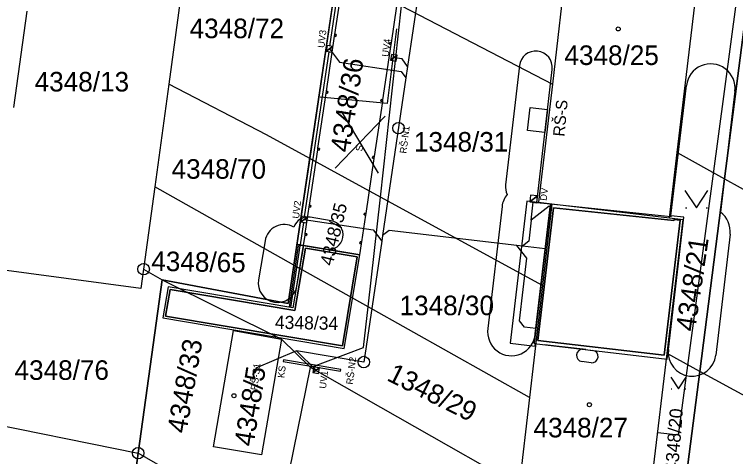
# Model space of a CAD drawing. Extents: x -735036 to -734743, y -1144813 to -1144181.
# Drawn here: x -734898.4 to -734835.7, y -1144564.1 to -1144525.7 of the extents above; entities that cross this region are included whole.
import ezdxf

# ---------------------------------------------------------------- set-up
doc = ezdxf.new("R2010")
doc.units = 0
for name, color, linetype in [('A3_BOURANÉ OBJEKTY', 7, 'Continuous'), ('A3_Netisk', 7, 'Continuous'), ('A3_ODVODŇOVACÍ ŽLAB', 7, 'Continuous'), ('A3_SIT_OBJEKTY_N01', 7, 'Continuous'), ('A3_SIT_PNB', 7, 'Continuous'), ('CKKOTY', 7, 'Continuous'), ('CKPLYN_POTRUBI_NT_PODZ_N', 7, 'Continuous'), ('CKSTENY_SRAF', 7, 'Continuous'), ('CKTEXTY_MALE', 7, 'Continuous'), ('Katastr_HRANICE DRÁHY', 7, 'Continuous'), ('Katastr_Hranice parcel', 7, 'Continuous'), ('Katastr_Parcelní čísla', 7, 'Continuous'), ('Katastr_Značky kultur', 7, 'Continuous'), ('SO01_CKKANALIZACE_JEDNOTNA_PODZ_N', 7, 'Continuous'), ('SO05_CKKANALIZACE_JEDNOTNA_PODZ_N', 7, 'Continuous')]:
    doc.layers.add(name, color=color, linetype=linetype)

msp = doc.modelspace()

# ---------------------------------------------------------------- linework, layer by layer
for p, q in [((-734871.293, -1144528.872), (-734870.725, -1144528.45)), ((-734865.695, -1144529.643), (-734865.127, -1144529.221)), ((-734853.579, -1144541.96), (-734852.914, -1144541.433)), ((-734873.494, -1144543.707), (-734872.926, -1144543.285)), ((-734872.456, -1144556.781), (-734871.88, -1144556.371))]:
    msp.add_line(p, q)
for points in [[(-734871.293, -1144528.872), (-734870.798, -1144528.945), (-734870.725, -1144528.45), (-734871.219, -1144528.377)], [(-734871.293, -1144528.872), (-734870.798, -1144528.945), (-734870.725, -1144528.45)], [(-734865.695, -1144529.643), (-734865.201, -1144529.716), (-734865.127, -1144529.221), (-734865.622, -1144529.148)], [(-734865.695, -1144529.643), (-734865.201, -1144529.716), (-734865.127, -1144529.221)], [(-734853.579, -1144541.96), (-734852.983, -1144542.029), (-734852.914, -1144541.433), (-734853.51, -1144541.364)], [(-734853.579, -1144541.96), (-734852.983, -1144542.029), (-734852.914, -1144541.433)], [(-734873.494, -1144543.707), (-734873, -1144543.78), (-734872.926, -1144543.285), (-734873.421, -1144543.212)], [(-734873.494, -1144543.707), (-734873, -1144543.78), (-734872.926, -1144543.285)], [(-734872.456, -1144556.781), (-734871.963, -1144556.864), (-734871.88, -1144556.371), (-734872.373, -1144556.288)], [(-734872.456, -1144556.781), (-734871.963, -1144556.864), (-734871.88, -1144556.371)]]:
    msp.add_lwpolyline(points, close=True)
at = {"layer": 'A3_BOURANÉ OBJEKTY'}
for p, q in [((-734866.175, -1144534.51), (-734870.526, -1144539.039)), ((-734866.751, -1144539.477), (-734869.95, -1144534.072))]:
    msp.add_line(p, q, dxfattribs=at)
msp.add_lwpolyline([(-734865.166, -1144526.906), (-734865.978, -1144533.409), (-734871.807, -1144532.846)], dxfattribs=at)
at = {"layer": 'A3_Netisk'}
for p, q in [((-734851.783, -1144542.154), (-734853.2, -1144554.266)), ((-734848.694, -1144554.798), (-734852.306, -1144554.375))]:
    msp.add_line(p, q, dxfattribs=at)
msp.add_lwpolyline([(-734852.04, -1144533.939), (-734852.27, -1144535.925), (-734853.791, -1144535.749), (-734853.561, -1144533.763)], close=True, dxfattribs=at)
at = {"layer": 'A3_ODVODŇOVACÍ ŽLAB'}
for points in [[(-734870.972, -1144528.414), (-734867.824, -1144507.227), (-734866.588, -1144507.411)], [(-734873.174, -1144543.249), (-734871.046, -1144528.908)], [(-734874.496, -1144551.113), (-734873.702, -1144545.773), (-734873.54, -1144545.701), (-734873.249, -1144543.743)]]:
    msp.add_lwpolyline(points, dxfattribs=at)
at = {"layer": 'A3_SIT_OBJEKTY_N01'}
for p, q in [((-734853.848, -1144541.911), (-734855.291, -1144554.247)), ((-734851.783, -1144542.154), (-734853.848, -1144541.911)), ((-734851.783, -1144542.154), (-734853.2, -1144554.27)), ((-734853.2, -1144554.27), (-734851.783, -1144542.154)), ((-734852.868, -1144554.007), (-734851.519, -1144542.484)), ((-734841.306, -1144543.249), (-734851.783, -1144542.154)), ((-734851.519, -1144542.484), (-734841.043, -1144543.578)), ((-734841.619, -1144555.625), (-734840.177, -1144543.299)), ((-734841.297, -1144543.168), (-734841.306, -1144543.249)), ((-734840.177, -1144543.299), (-734841.297, -1144543.168)), ((-734840.51, -1144543.563), (-734841.883, -1144555.293)), ((-734841.043, -1144543.578), (-734841.034, -1144543.501)), ((-734841.034, -1144543.501), (-734840.51, -1144543.563)), ((-734873.262, -1144545.743), (-734874.2, -1144551.163)), ((-734868.356, -1144546.569), (-734873.262, -1144545.743)), ((-734874.036, -1144551.393), (-734873.099, -1144545.974)), ((-734873.099, -1144545.974), (-734868.587, -1144546.733)), ((-734868.587, -1144546.733), (-734869.889, -1144554.474)), ((-734869.725, -1144554.704), (-734868.356, -1144546.569)), ((-734885.047, -1144549.338), (-734885.503, -1144552.05)), ((-734885.273, -1144551.886), (-734884.883, -1144549.568)), ((-734874.2, -1144551.163), (-734885.047, -1144549.338)), ((-734884.883, -1144549.568), (-734874.036, -1144551.393)), ((-734885.503, -1144552.05), (-734869.725, -1144554.704)), ((-734869.889, -1144554.474), (-734885.273, -1144551.886)), ((-734841.883, -1144555.293), (-734852.868, -1144554.007)), ((-734855.291, -1144554.247), (-734853.107, -1144554.503)), ((-734853.2, -1144554.27), (-734841.619, -1144555.625)), ((-734853.081, -1144554.284), (-734853.2, -1144554.27)), ((-734853.107, -1144554.503), (-734853.081, -1144554.284)), ((-734875, -1144555.695), (-734875.026, -1144555.843)), ((-734875.026, -1144555.843), (-734870.057, -1144556.677)), ((-734870.032, -1144556.529), (-734875, -1144555.695)), ((-734870.057, -1144556.677), (-734870.032, -1144556.529))]:
    msp.add_line(p, q, dxfattribs=at)
for points in [[(-734888.44, -1144569.554), (-734887.65, -1144563.8), (-734885.58, -1144548.75), (-734874.6, -1144550.79), (-734868.084, -1144506.936)], [(-734833.069, -1144512.138), (-734834.23, -1144521.36), (-734836.63, -1144539.96), (-734838.79, -1144556.7), (-734840.06, -1144566.59), (-734840.228, -1144567.714), (-734841.06, -1144574.32)], [(-734869.856, -1144522.605), (-734870.569, -1144527.402), (-734870.421, -1144527.424), (-734870.443, -1144527.572), (-734870.591, -1144527.55), (-734871.304, -1144532.348), (-734871.156, -1144532.37), (-734871.178, -1144532.518), (-734871.326, -1144532.496), (-734872.039, -1144537.293), (-734871.89, -1144537.315), (-734871.912, -1144537.464), (-734872.061, -1144537.442), (-734872.774, -1144542.239), (-734872.625, -1144542.261), (-734872.647, -1144542.41), (-734872.796, -1144542.387), (-734873.141, -1144544.712), (-734872.993, -1144544.734), (-734873.015, -1144544.882), (-734873.163, -1144544.86), (-734873.293, -1144545.738), (-734868.362, -1144546.568), (-734868.217, -1144545.595), (-734868.366, -1144545.573), (-734868.344, -1144545.425), (-734868.195, -1144545.447), (-734867.85, -1144543.122), (-734867.998, -1144543.1), (-734867.976, -1144542.952), (-734867.828, -1144542.974), (-734867.115, -1144538.177), (-734867.263, -1144538.155), (-734867.241, -1144538.006), (-734867.093, -1144538.028), (-734866.38, -1144533.231), (-734866.529, -1144533.209), (-734866.507, -1144533.06), (-734866.358, -1144533.082), (-734865.645, -1144528.285), (-734865.794, -1144528.263), (-734865.772, -1144528.115), (-734865.623, -1144528.137), (-734864.911, -1144523.339)], [(-734870.421, -1144527.424), (-734870.569, -1144527.402), (-734870.591, -1144527.55), (-734870.443, -1144527.572), (-734870.421, -1144527.424)], [(-734865.623, -1144528.137), (-734865.772, -1144528.115), (-734865.794, -1144528.263), (-734865.645, -1144528.285), (-734865.623, -1144528.137)], [(-734871.156, -1144532.37), (-734871.304, -1144532.348), (-734871.326, -1144532.496), (-734871.178, -1144532.518), (-734871.156, -1144532.37)], [(-734866.358, -1144533.082), (-734866.507, -1144533.06), (-734866.529, -1144533.209), (-734866.38, -1144533.231), (-734866.358, -1144533.082)], [(-734871.89, -1144537.315), (-734872.039, -1144537.293), (-734872.061, -1144537.442), (-734871.912, -1144537.464), (-734871.89, -1144537.315)], [(-734867.093, -1144538.028), (-734867.241, -1144538.006), (-734867.263, -1144538.155), (-734867.115, -1144538.177), (-734867.093, -1144538.028)], [(-734872.625, -1144542.261), (-734872.774, -1144542.239), (-734872.796, -1144542.387), (-734872.647, -1144542.41), (-734872.625, -1144542.261)], [(-734867.828, -1144542.974), (-734867.976, -1144542.952), (-734867.998, -1144543.1), (-734867.85, -1144543.122), (-734867.828, -1144542.974)], [(-734873.163, -1144544.86), (-734873.015, -1144544.882), (-734872.993, -1144544.734), (-734873.141, -1144544.712), (-734873.163, -1144544.86)], [(-734873.262, -1144545.743), (-734873.293, -1144545.738), (-734873.603, -1144545.787), (-734874.397, -1144551.13)], [(-734868.195, -1144545.447), (-734868.344, -1144545.425), (-734868.366, -1144545.573), (-734868.217, -1144545.595), (-734868.195, -1144545.447)]]:
    msp.add_lwpolyline(points, dxfattribs=at)
for points in [[(-734841.297, -1144543.168), (-734841.306, -1144543.249), (-734851.783, -1144542.154), (-734853.2, -1144554.27), (-734841.619, -1144555.625), (-734840.177, -1144543.299)], [(-734841.034, -1144543.501), (-734841.043, -1144543.578), (-734851.519, -1144542.484), (-734852.868, -1144554.007), (-734841.883, -1144555.293), (-734840.51, -1144543.563)], [(-734869.725, -1144554.704), (-734868.356, -1144546.569), (-734873.262, -1144545.743), (-734874.2, -1144551.163), (-734885.047, -1144549.338), (-734885.503, -1144552.05)], [(-734869.889, -1144554.474), (-734868.587, -1144546.733), (-734873.099, -1144545.974), (-734874.036, -1144551.393), (-734884.883, -1144549.568), (-734885.273, -1144551.886)], [(-734875.026, -1144555.843), (-734870.057, -1144556.677), (-734870.032, -1144556.529), (-734875, -1144555.695)]]:
    msp.add_lwpolyline(points, close=True, dxfattribs=at)
at = {"layer": 'A3_SIT_PNB'}
for points in [[(-734854.49, -1144530.117), (-734855.694, -1144540.487)], [(-734851.783, -1144542.154), (-734852.983, -1144542.029), (-734851.639, -1144530.45)], [(-734841.297, -1144543.168), (-734839.952, -1144531.834)], [(-734835.742, -1144532.333), (-734836.991, -1144542.861)], [(-734855.997, -1144542.375), (-734857.235, -1144552.957)], [(-734853.103, -1144553.441), (-734851.783, -1144542.154)], [(-734870.874, -1144543.6), (-734872.698, -1144543.293)], [(-734841.522, -1144554.796), (-734840.177, -1144543.299), (-734841.297, -1144543.168), (-734841.297, -1144543.168)], [(-734836.162, -1144544.775), (-734837.391, -1144555.279)], [(-734876.611, -1144545.332), (-734877.183, -1144548.734)], [(-734873.86, -1144549.293), (-734873.287, -1144545.891), (-734873.262, -1144545.743), (-734873.114, -1144545.768), (-734871.29, -1144546.075)], [(-734848.915, -1144554.772), (-734848.12, -1144554.865)], [(-734848.246, -1144555.937), (-734849.04, -1144555.844)]]:
    msp.add_lwpolyline(points, dxfattribs=at)
for centre, radius, start, end in [((-734853.064, -1144530.283), 1.435, 353.33341, 173.32709), ((-734837.847, -1144532.083), 2.12, 353.23643, 173.23644), ((-734854.268, -1144540.654), 1.435, 173.32808, 207.03421), ((-734853.931, -1144542.616), 2.08, 140.96329, 173.32599), ((-734872.906, -1144544.531), 1.255, 80.4474, 162.539), ((-734838.227, -1144544.534), 2.08, 353.32599, 53.51095), ((-734874.949, -1144545.612), 1.685, 59.88428, 170.44851), ((-734871.082, -1144544.838), 1.255, 260.44926, 80.44926), ((-734875.521, -1144549.014), 1.685, 170.44926, 350.44926), ((-734855.176, -1144553.254), 2.081, 171.79921, 354.85276), ((-734848.977, -1144555.308), 0.54, 83.32837, 263.32599), ((-734848.977, -1144555.303), 0.535, 83.32351, 83.32831), ((-734848.183, -1144555.401), 0.54, 263.32927, 83.32599), ((-734839.457, -1144555.038), 2.08, 173.32599, 353.32599)]:
    msp.add_arc(centre, radius, start, end, dxfattribs=at)
at = {"layer": 'CKKOTY'}
msp.add_line((-734873.293, -1144545.738), (-734873.787, -1144545.665), dxfattribs=at)
at = {"layer": 'CKPLYN_POTRUBI_NT_PODZ_N'}
msp.add_line((-734840.638, -1144562.238), (-734842.453, -1144562.022), dxfattribs=at)
msp.add_lwpolyline([(-734840.638, -1144562.238), (-734835.108, -1144520.855), (-734845.346, -1144519.67)], dxfattribs=at)
at = {"layer": 'CKSTENY_SRAF'}
msp.add_line((-734885.58, -1144548.75), (-734886.194, -1144553.213), dxfattribs=at)
at = {"layer": 'CKTEXTY_MALE'}
for points in [[(-734873.87, -1144554.906), (-734877.406, -1144556.428)], [(-734877.406, -1144556.428), (-734877.429, -1144556.626)]]:
    msp.add_lwpolyline(points, dxfattribs=at)
at = {"layer": 'Katastr_HRANICE DRÁHY'}
for points in [[(-734882.78, -1144515.44), (-734885, -1144531.74)], [(-734836.63, -1144539.96), (-734834.23, -1144521.36)], [(-734898.48, -1144533.77), (-734897.31, -1144525.39)], [(-734885, -1144531.74), (-734886.21, -1144540.66)], [(-734838.79, -1144556.7), (-734836.63, -1144539.96)], [(-734886.21, -1144540.66), (-734887.18, -1144547.81)], [(-734887.18, -1144547.81), (-734885.58, -1144548.75)], [(-734885.58, -1144548.75), (-734887.65, -1144563.8)], [(-734840.06, -1144566.59), (-734838.79, -1144556.7)], [(-734887.65, -1144563.8), (-734889.5, -1144577.27)]]:
    msp.add_lwpolyline(points, dxfattribs=at)
at = {"layer": 'Katastr_Hranice parcel'}
for points in [[(-734850.35, -1144520.8), (-734851.62, -1144531.72)], [(-734870.33, -1144522.02), (-734872.73, -1144538.19)], [(-734840.76, -1144537.68), (-734838.91, -1144522.14)], [(-734866.58, -1144541.54), (-734864.73, -1144524.92)], [(-734864.73, -1144524.92), (-734851.62, -1144531.72)], [(-734876.5, -1144536.13), (-734885, -1144531.74)], [(-734851.62, -1144531.72), (-734852.82, -1144541.99)], [(-734872.73, -1144538.19), (-734876.5, -1144536.13)], [(-734841.43, -1144543.35), (-734840.76, -1144537.68)], [(-734840.76, -1144537.68), (-734836.63, -1144539.96)], [(-734872.73, -1144538.19), (-734874.11, -1144547.46)], [(-734866.58, -1144541.54), (-734872.73, -1144538.19)], [(-734836.63, -1144539.96), (-734832.56, -1144542.21)], [(-734874.11, -1144547.46), (-734886.21, -1144540.66)], [(-734867.65, -1144551.09), (-734866.58, -1144541.54)], [(-734852.48, -1144549.23), (-734866.58, -1144541.54)], [(-734852.82, -1144541.99), (-734851.65, -1144542.13)], [(-734851.65, -1144542.13), (-734852.48, -1144549.23)], [(-734851.65, -1144542.13), (-734841.43, -1144543.35)], [(-734841.43, -1144543.35), (-734840.25, -1144543.49)], [(-734841.63, -1144555.15), (-734840.25, -1144543.49)], [(-734887.41, -1144549.49), (-734900.43, -1144547.74)], [(-734874.11, -1144547.46), (-734874.6, -1144550.79)], [(-734867.65, -1144551.09), (-734874.11, -1144547.46)], [(-734887.18, -1144547.81), (-734887.41, -1144549.49)], [(-734874.6, -1144550.79), (-734885.58, -1144548.75)], [(-734885.58, -1144548.75), (-734875.18, -1144553.88)], [(-734852.48, -1144549.23), (-734853.62, -1144558.97)], [(-734868.04, -1144554.63), (-734867.65, -1144551.09)], [(-734853.62, -1144558.97), (-734867.65, -1144551.09)], [(-734881.1, -1144563.24), (-734879.37, -1144553.15)], [(-734879.37, -1144553.15), (-734875.18, -1144553.88)], [(-734875.18, -1144553.88), (-734876.93, -1144563.95)], [(-734875.18, -1144553.88), (-734872.67, -1144556.37)], [(-734872.67, -1144556.37), (-734868.04, -1144554.63)], [(-734842.81, -1144565.04), (-734841.63, -1144555.15)], [(-734838.79, -1144556.7), (-734841.63, -1144555.15)], [(-734875.6, -1144570.76), (-734872.67, -1144556.37)], [(-734854.52, -1144566.67), (-734872.67, -1144556.37)], [(-734834.48, -1144559.05), (-734838.79, -1144556.7)], [(-734853.62, -1144558.97), (-734854.52, -1144566.67)], [(-734902.26, -1144560.85), (-734887.65, -1144563.8)], [(-734876.93, -1144563.95), (-734881.1, -1144563.24)], [(-734875.6, -1144570.76), (-734887.65, -1144563.8)]]:
    msp.add_lwpolyline(points, dxfattribs=at)
at = {"layer": 'Katastr_Značky kultur'}
for p, q in [((-734840.03, -1144542.48), (-734839.93, -1144542.48)), ((-734838.23, -1144542.48), (-734838.13, -1144542.48)), ((-734887.23, -1144547.81), (-734887.13, -1144547.81)), ((-734841.31, -1144557.195), (-734840.64, -1144558.2)), ((-734840.64, -1144558.2), (-734839.97, -1144557.195)), ((-734841.277, -1144558.2), (-734841.21, -1144558.2)), ((-734840.071, -1144558.2), (-734840.003, -1144558.2)), ((-734887.7, -1144563.8), (-734887.6, -1144563.8))]:
    msp.add_line(p, q, dxfattribs=at)
msp.add_lwpolyline([(-734840.08, -1144540.98), (-734839.08, -1144542.48), (-734838.08, -1144540.98)], dxfattribs=at)
for centre, radius in [((-734845.89, -1144526.93), 0.175), ((-734887.18, -1144547.81), 0.499), ((-734879.32, -1144558.81), 0.175), ((-734848.4, -1144559.59), 0.175), ((-734887.65, -1144563.8), 0.499)]:
    msp.add_circle(centre, radius, dxfattribs=at)
at = {"layer": 'SO01_CKKANALIZACE_JEDNOTNA_PODZ_N'}
msp.add_line((-734853.457, -1144543.555), (-734853.276, -1144541.995), dxfattribs=at)
for points in [[(-734851.904, -1144542.327), (-734853.457, -1144543.555), (-734853.669, -1144545.365), (-734854.223, -1144545.804)], [(-734852.237, -1144546.036), (-734854.223, -1144545.804), (-734854.72, -1144545.746), (-734865.823, -1144544.448), (-734866.393, -1144544.885)], [(-734853.049, -1144552.979), (-734854.043, -1144552.863), (-734854.481, -1144552.308), (-734853.843, -1144546.855), (-734854.72, -1144545.746)]]:
    msp.add_lwpolyline(points, dxfattribs=at)
at = {"layer": 'SO05_CKKANALIZACE_JEDNOTNA_PODZ_N'}
msp.add_line((-734872.168, -1144556.576), (-734873.869, -1144554.902), dxfattribs=at)
for points in [[(-734866.341, -1144507.447), (-734861.751, -1144513.639), (-734864.21, -1144530.193), (-734864.357, -1144531.183), (-734866.393, -1144544.885), (-734866.467, -1144545.379), (-734868.027, -1144555.885), (-734873.869, -1144554.902)], [(-734871.009, -1144528.661), (-734870.152, -1144529.816), (-734864.775, -1144530.615), (-734864.357, -1144531.183)], [(-734864.21, -1144530.193), (-734864.695, -1144529.538), (-734865.411, -1144529.432)], [(-734873.21, -1144543.496), (-734867.201, -1144544.389), (-734866.467, -1144545.379)]]:
    msp.add_lwpolyline(points, dxfattribs=at)
for centre in [(-734865.006, -1144535.549), (-734868.027, -1144555.884)]:
    msp.add_circle(centre, 0.5, dxfattribs=at)

# ---------------------------------------------------------------- texts
at = {"layer": 'A3_Netisk'}
msp.add_text('RŠ-S', height=1, rotation=84.74142, dxfattribs=at).set_placement((-734850.57, -1144536.314))
at = {"layer": 'CKTEXTY_MALE'}
for s, rotation, p in [('UV3', 83.326, (-734871.455, -1144528.601)), ('UV4', 83.326, (-734865.857, -1144529.372)), ('RŠ-N1', 83.326, (-734864.312, -1144537.784)), ('S', 83.326, (-734868.143, -1144537.587)), ('DV', 83.326, (-734852.12, -1144541.888)), ('UV2', 83.326, (-734873.659, -1144543.438)), ('RŠ-N2', 83.326, (-734868.964, -1144557.864)), ('RŠ-S1', 83.32599, (-734877.284, -1144558.362)), ('KS', 83.326, (-734874.936, -1144557.297)), ('UV1', 83.326, (-734871.316, -1144558.219))]:
    msp.add_text(s, height=0.6, rotation=rotation, dxfattribs=at).set_placement(p)
at = {"layer": 'Katastr_Parcelní čísla'}
for s, p in [('4348/72', (-734883.177, -1144527.73)), ('4348/25', (-734850.567, -1144530.06)), ('4348/13', (-734896.662, -1144532.363)), ('1348/31', (-734863.663, -1144537.59)), ('4348/70', (-734884.747, -1144539.95)), ('1348/30', (-734864.914, -1144551.81)), ('4348/76', (-734898.411, -1144557.43)), ('4348/27', (-734853.257, -1144562.43))]:
    msp.add_text(s, height=1.7, dxfattribs=at).set_placement(p)
for s, height, rotation, p in [('4348/36', 1.7, 81.4482, (-734869.257, -1144537.728)), ('4348/35', 1.14, 76.51791, (-734870.739, -1144547.577)), ('4348/21', 1.7, 81.57303, (-734839.215, -1144553.287)), ('4348/65', 1.7, 358.90416, (-734886.526, -1144547.947)), ('4348/34', 1.14, 358.85997, (-734875.77, -1144552.985)), ('4348/33', 1.7, 80.02647, (-734883.471, -1144562.144)), ('4348/5', 1.7, 80.96139, (-734877.631, -1144563.281)), ('1348/29', 1.7, 333.39276, (-734866.103, -1144557.435)), ('4348/20', 1.14, 85.455, (-734840.688, -1144565.457))]:
    msp.add_text(s, height=height, rotation=rotation, dxfattribs=at).set_placement(p)

doc.saveas('drawing.dxf')
